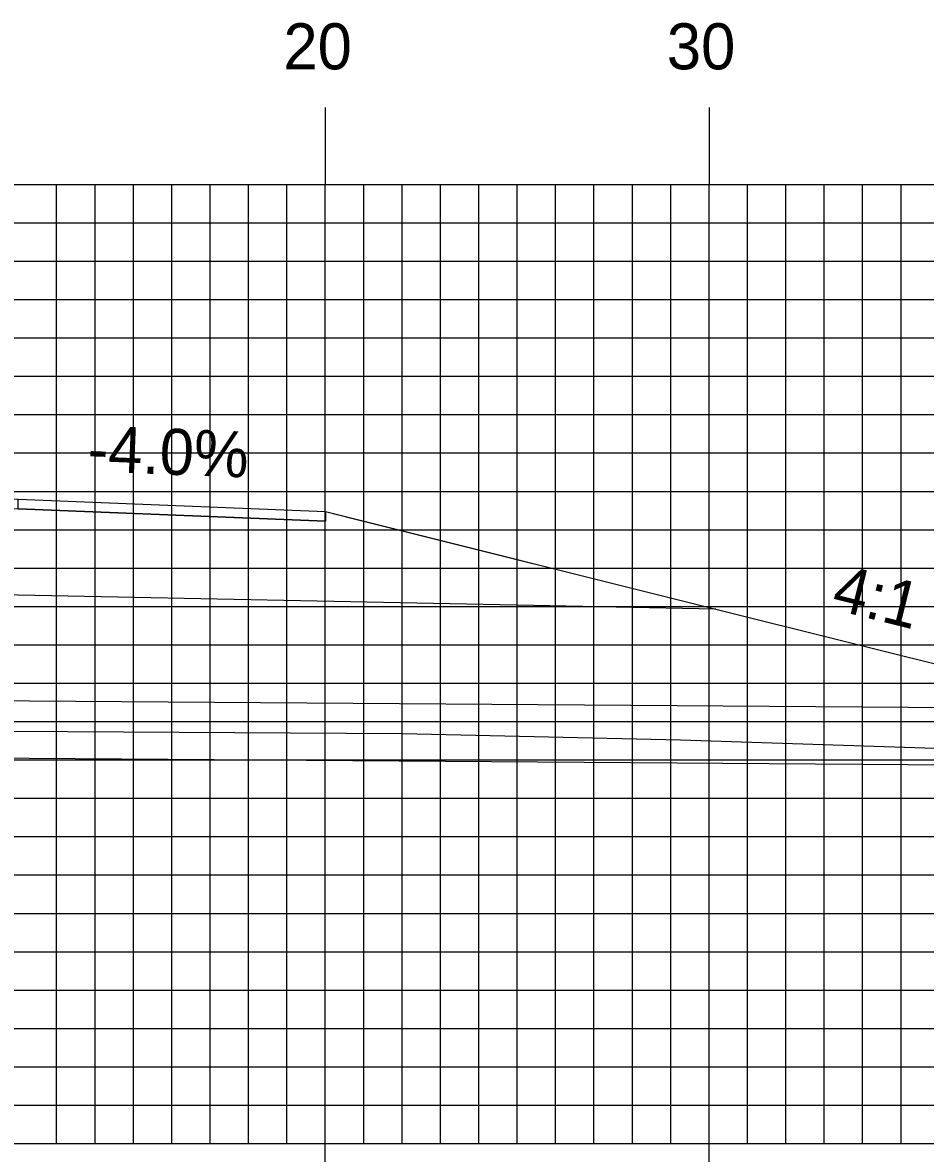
# Model space of a CAD drawing. Extents: x 1771629 to 1771972, y 442591 to 442811.
# Drawn here: x 1771806.69 to 1771830.21, y 442608.41 to 442637.88 of the extents above; entities that cross this region are included whole.
import ezdxf

# ---------------------------------------------------------------- set-up
doc = ezdxf.new("R2010")
doc.units = 0
for name, color, linetype in [('ANNOTATION', 7, 'Continuous'), ('D_Drainage_Culvert', 7, 'Continuous'), ('D_Roadway_Centerline', 7, 'Continuous'), ('D_Roadway_Edge_Shoulder', 7, 'Continuous'), ('D_Roadway_SlopeLines', 7, 'Continuous'), ('D_Roadway_SubGrade', 7, 'Continuous'), ('H_V ANNOTATION', 7, 'Continuous'), ('MAJOR', 7, 'Continuous'), ('MINOR', 7, 'Continuous'), ('S_Roadway_Centerline', 7, 'Continuous')]:
    doc.layers.add(name, color=color, linetype=linetype)

msp = doc.modelspace()

# ---------------------------------------------------------------- linework, layer by layer
at = {"layer": 'D_Drainage_Culvert'}
msp.add_lwpolyline([(1771755.035, 442620.574), (1771843.033, 442619.942), (1771843.022, 442618.442), (1771755.024, 442619.074)], close=True, dxfattribs=at)
at = {"layer": 'D_Roadway_Centerline'}
msp.add_lwpolyline([(1771759.741, 442621.427), (1771761.259, 442621.807), (1771762.581, 442622.137), (1771763.873, 442622.461), (1771764.406, 442622.594), (1771765.674, 442622.911), (1771774.58, 442625.137), (1771782.578, 442625.457), (1771782.581, 442625.457), (1771782.585, 442625.457), (1771789.339, 442625.592), (1771794.581, 442625.697), (1771794.589, 442625.697), (1771806.58, 442625.457), (1771814.581, 442625.137), (1771815.296, 442624.958), (1771824.751, 442622.595), (1771824.755, 442622.594), (1771831.544, 442620.896)], dxfattribs=at)
at = {"layer": 'D_Roadway_Edge_Shoulder'}
msp.add_lwpolyline([(1771806.58, 442625.457), (1771814.581, 442625.137), (1771814.581, 442624.887), (1771806.58, 442625.207)], close=True, dxfattribs=at)
at = {"layer": 'D_Roadway_SlopeLines'}
msp.add_lwpolyline([(1771814.581, 442625.137), (1771824.755, 442622.594), (1771831.544, 442620.896)], dxfattribs=at)
at = {"layer": 'D_Roadway_SubGrade'}
msp.add_lwpolyline([(1771782.581, 442622.957), (1771764.406, 442622.594), (1771774.58, 442625.137), (1771774.58, 442624.887), (1771782.581, 442625.207), (1771794.581, 442625.447), (1771806.58, 442625.207), (1771814.581, 442624.887), (1771814.581, 442625.137), (1771824.755, 442622.594), (1771806.58, 442622.957), (1771794.581, 442623.197)], close=True, dxfattribs=at)
at = {"layer": 'MAJOR'}
for p, q in [((1771814.58, 442635.669), (1771814.58, 442633.665)), ((1771824.58, 442635.669), (1771824.58, 442633.665)), ((1771654.58, 442633.665), (1771934.58, 442633.665)), ((1771654.58, 442633.665), (1771934.58, 442633.665)), ((1771814.58, 442608.665), (1771814.58, 442633.665)), ((1771824.58, 442608.665), (1771824.58, 442633.665)), ((1771654.58, 442628.665), (1771934.58, 442628.665)), ((1771654.58, 442623.665), (1771934.58, 442623.665)), ((1771654.58, 442618.665), (1771934.58, 442618.665)), ((1771654.58, 442613.665), (1771934.58, 442613.665)), ((1771654.58, 442608.665), (1771934.58, 442608.665)), ((1771654.58, 442608.665), (1771934.58, 442608.665)), ((1771814.58, 442606.661), (1771814.58, 442608.665)), ((1771824.58, 442606.661), (1771824.58, 442608.665))]:
    msp.add_line(p, q, dxfattribs=at)
at = {"layer": 'MINOR'}
for p, q in [((1771807.58, 442608.665), (1771807.58, 442633.665)), ((1771808.58, 442608.665), (1771808.58, 442633.665)), ((1771809.58, 442608.665), (1771809.58, 442633.665)), ((1771810.58, 442608.665), (1771810.58, 442633.665)), ((1771811.58, 442608.665), (1771811.58, 442633.665)), ((1771812.58, 442608.665), (1771812.58, 442633.665)), ((1771813.58, 442608.665), (1771813.58, 442633.665)), ((1771815.58, 442608.665), (1771815.58, 442633.665)), ((1771816.58, 442608.665), (1771816.58, 442633.665)), ((1771817.58, 442608.665), (1771817.58, 442633.665)), ((1771818.58, 442608.665), (1771818.58, 442633.665)), ((1771819.58, 442608.665), (1771819.58, 442633.665)), ((1771820.58, 442608.665), (1771820.58, 442633.665)), ((1771821.58, 442608.665), (1771821.58, 442633.665)), ((1771822.58, 442608.665), (1771822.58, 442633.665)), ((1771823.58, 442608.665), (1771823.58, 442633.665)), ((1771825.58, 442608.665), (1771825.58, 442633.665)), ((1771826.58, 442608.665), (1771826.58, 442633.665)), ((1771827.58, 442608.665), (1771827.58, 442633.665)), ((1771828.58, 442608.665), (1771828.58, 442633.665)), ((1771829.58, 442608.665), (1771829.58, 442633.665)), ((1771654.58, 442632.665), (1771934.58, 442632.665)), ((1771654.58, 442631.665), (1771934.58, 442631.665)), ((1771654.58, 442630.665), (1771934.58, 442630.665)), ((1771654.58, 442629.665), (1771934.58, 442629.665)), ((1771654.58, 442627.665), (1771934.58, 442627.665)), ((1771654.58, 442626.665), (1771934.58, 442626.665)), ((1771654.58, 442625.665), (1771934.58, 442625.665)), ((1771654.58, 442624.665), (1771934.58, 442624.665)), ((1771654.58, 442622.665), (1771934.58, 442622.665)), ((1771654.58, 442621.665), (1771934.58, 442621.665)), ((1771654.58, 442620.665), (1771934.58, 442620.665)), ((1771654.58, 442619.665), (1771934.58, 442619.665)), ((1771654.58, 442617.665), (1771934.58, 442617.665)), ((1771654.58, 442616.665), (1771934.58, 442616.665)), ((1771654.58, 442615.665), (1771934.58, 442615.665)), ((1771654.58, 442614.665), (1771934.58, 442614.665)), ((1771654.58, 442612.665), (1771934.58, 442612.665)), ((1771654.58, 442611.665), (1771934.58, 442611.665)), ((1771654.58, 442610.665), (1771934.58, 442610.665)), ((1771654.58, 442609.665), (1771934.58, 442609.665))]:
    msp.add_line(p, q, dxfattribs=at)
at = {"layer": 'S_Roadway_Centerline'}
msp.add_lwpolyline([(1771735.693, 442620.673), (1771741.62, 442620.724), (1771750.71, 442620.542), (1771753.896, 442620.449), (1771755.85, 442620.471), (1771771.303, 442620.344), (1771776.843, 442620.306), (1771777.606, 442620.288), (1771778.581, 442620.28), (1771796.912, 442619.652), (1771806.41, 442619.413), (1771816.58, 442619.351), (1771823.837, 442619.187), (1771834.719, 442618.832), (1771836.337, 442618.77), (1771837.241, 442618.711), (1771847.903, 442618.211), (1771857.287, 442617.889)], dxfattribs=at)

# ---------------------------------------------------------------- texts
at = {"layer": 'ANNOTATION'}
for s, rotation, p in [('-4.0%', 357.7094, (1771808.372, 442626.187)), ('4:1', 345.9665, (1771827.73, 442622.607))]:
    msp.add_text(s, height=1.2, rotation=rotation, dxfattribs=at).set_placement(p)
at = {"layer": 'H_V ANNOTATION'}
for s, p in [('20', (1771813.488, 442636.665)), ('30', (1771823.478, 442636.665))]:
    msp.add_text(s, height=1.2, dxfattribs=at).set_placement(p)

doc.saveas('drawing.dxf')
